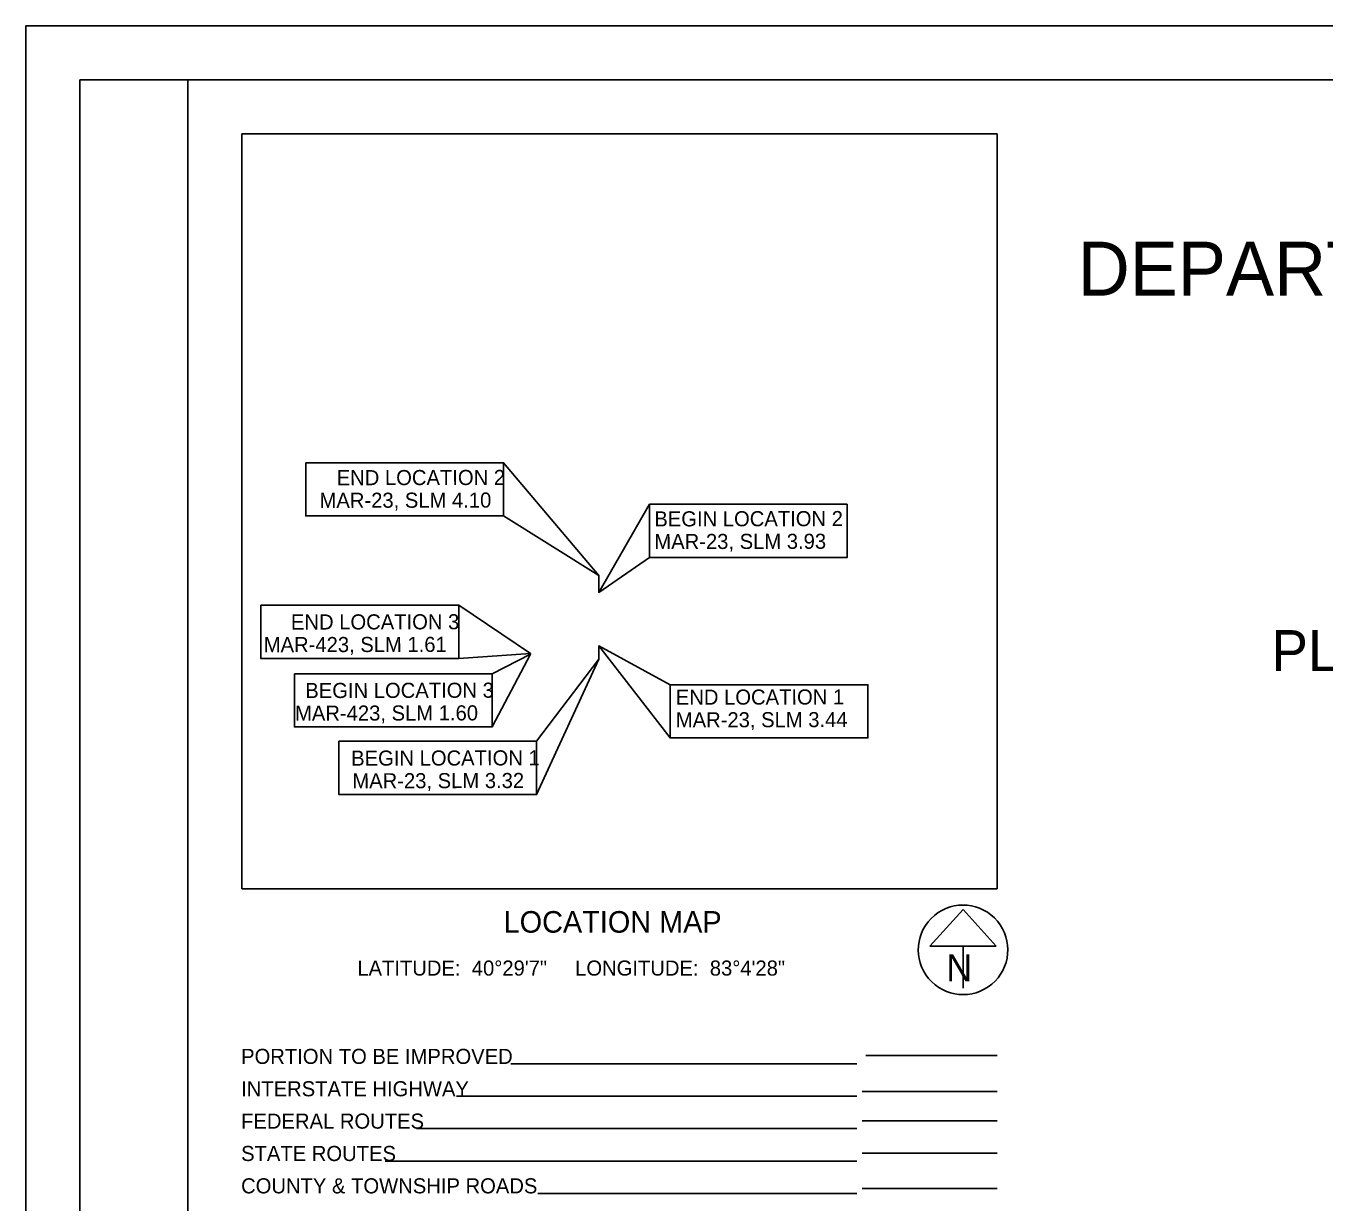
# Model space of a CAD drawing. Extents: x 0 to 34, y 0 to 22.
# Drawn here: x 0 to 12.03, y 11.1 to 22 of the extents above; entities that cross this region are included whole.
import ezdxf

# ---------------------------------------------------------------- set-up
doc = ezdxf.new("R2010")
doc.units = 0
for name, color, linetype in [('SH_Border', 7, 'Continuous'), ('SH_Cut_Line', 7, 'Continuous'), ('SH_Data', 7, 'Continuous'), ('SH_Text', 7, 'Continuous')]:
    doc.layers.add(name, color=color, linetype=linetype)

msp = doc.modelspace()

# ---------------------------------------------------------------- linework, layer by layer
at = {"layer": 'SH_Border'}
for points in [[(0.5, 21.5), (1.5, 21.5), (1.5, 0.5), (0.5, 0.5)], [(1.5, 21.5), (33.5, 21.5), (33.5, 0.5), (1.5, 0.5)]]:
    msp.add_lwpolyline(points, close=True, dxfattribs=at)
at = {"layer": 'SH_Cut_Line'}
msp.add_lwpolyline([(0, 0), (34, 0), (34, 22), (0, 22)], close=True, dxfattribs=at)
at = {"layer": 'SH_Data'}
for p, q in [((2, 21), (9, 21)), ((2, 21), (2, 14)), ((9, 21), (9, 14)), ((2, 14), (9, 14)), ((8.685, 13.809), (8.377, 13.468)), ((8.992, 13.468), (8.685, 13.809)), ((8.377, 13.468), (8.992, 13.468)), ((8.685, 13.468), (8.685, 13.081)), ((8.685, 13.435), (8.685, 13.435)), ((8.685, 13.435), (8.685, 13.435)), ((7.783, 12.455), (9, 12.455)), ((7.7, 12.377), (4.494, 12.377)), ((7.7, 12.077), (3.99, 12.077)), ((9, 12.121), (7.75, 12.121)), ((9, 11.849), (7.75, 11.849)), ((7.7, 11.777), (3.619, 11.777)), ((7.7, 11.477), (3.329, 11.477)), ((9, 11.549), (7.75, 11.549)), ((9, 11.222), (7.75, 11.222)), ((7.7, 11.177), (4.745, 11.177))]:
    msp.add_line(p, q, dxfattribs=at)
msp.add_arc((8.685, 13.435), 0.415, 129.7798, 129.7633, dxfattribs=at)
at = {"layer": 'SH_Text'}
for p, q in [((5.309, 16.904), (5.309, 16.832)), ((5.309, 16.832), (5.309, 16.748)), ((5.308, 16.185), (5.308, 16.253)), ((4.676, 16.181), (4.677, 16.177)), ((5.308, 16.185), (5.308, 16.129))]:
    msp.add_line(p, q, dxfattribs=at)
for points in [[(2.593, 17.951), (4.426, 17.951), (4.426, 17.457), (2.593, 17.457)], [(4.426, 17.951), (5.309, 16.904), (4.426, 17.457)], [(5.778, 17.566), (5.309, 16.748), (5.778, 17.072)], [(5.778, 17.566), (7.61, 17.566), (7.61, 17.072), (5.778, 17.072)], [(2.178, 16.629), (4.011, 16.629), (4.011, 16.135), (2.178, 16.135)], [(4.011, 16.135), (4.676, 16.181), (4.011, 16.629)], [(5.97, 15.893), (5.308, 16.253), (5.97, 15.399)], [(4.32, 15.501), (4.677, 16.177), (4.32, 15.995)], [(4.733, 14.874), (5.308, 16.129), (4.733, 15.368)], [(2.488, 15.995), (4.32, 15.995), (4.32, 15.501), (2.488, 15.501)], [(5.97, 15.893), (7.803, 15.893), (7.803, 15.399), (5.97, 15.399)], [(2.9, 15.368), (4.733, 15.368), (4.733, 14.874), (2.9, 14.874)]]:
    msp.add_lwpolyline(points, close=True, dxfattribs=at)

# ---------------------------------------------------------------- texts
at = {"layer": 'SH_Data'}
msp.add_text('N', height=0.25, dxfattribs=at).set_placement((8.529, 13.144))
at = {"layer": 'SH_Text'}
for s, height, p in [('DEPARTMENT OF TRANSPORTATION', 0.5, (9.747, 19.5)), ('PLEASANT, WALDO & RICHLAND TOWNSHIPS', 0.38, (11.543, 16.019)), ('LOCATION MAP', 0.2, (4.427, 13.594)), ('LATITUDE:  40°29\'7"     LONGITUDE:  83°4\'28"', 0.14, (3.071, 13.196)), ('PORTION TO BE IMPROVED', 0.14, (1.994, 12.377)), ('INTERSTATE HIGHWAY', 0.14, (1.994, 12.077)), ('FEDERAL ROUTES', 0.14, (1.994, 11.777)), ('STATE ROUTES', 0.14, (1.994, 11.477)), ('COUNTY & TOWNSHIP ROADS', 0.14, (1.994, 11.177))]:
    msp.add_text(s, height=height, dxfattribs=at).set_placement(p)
for s, p in [('END LOCATION 2', (2.88, 17.742)), ('MAR-23, SLM 4.10', (2.721, 17.532)), ('BEGIN LOCATION 2', (5.824, 17.36)), ('MAR-23, SLM 3.93', (5.824, 17.15)), ('END LOCATION 3', (2.456, 16.404)), ('MAR-423, SLM 1.61', (2.204, 16.194)), ('BEGIN LOCATION 3', (2.589, 15.769)), ('END LOCATION 1', (6.023, 15.707)), ('MAR-423, SLM 1.60', (2.494, 15.559)), ('MAR-23, SLM 3.44', (6.023, 15.497)), ('BEGIN LOCATION 1', (3.014, 15.142)), ('MAR-23, SLM 3.32', (3.025, 14.932))]:
    msp.add_text(s, height=0.14, rotation=0.1007, dxfattribs=at).set_placement(p)

doc.saveas('drawing.dxf')
